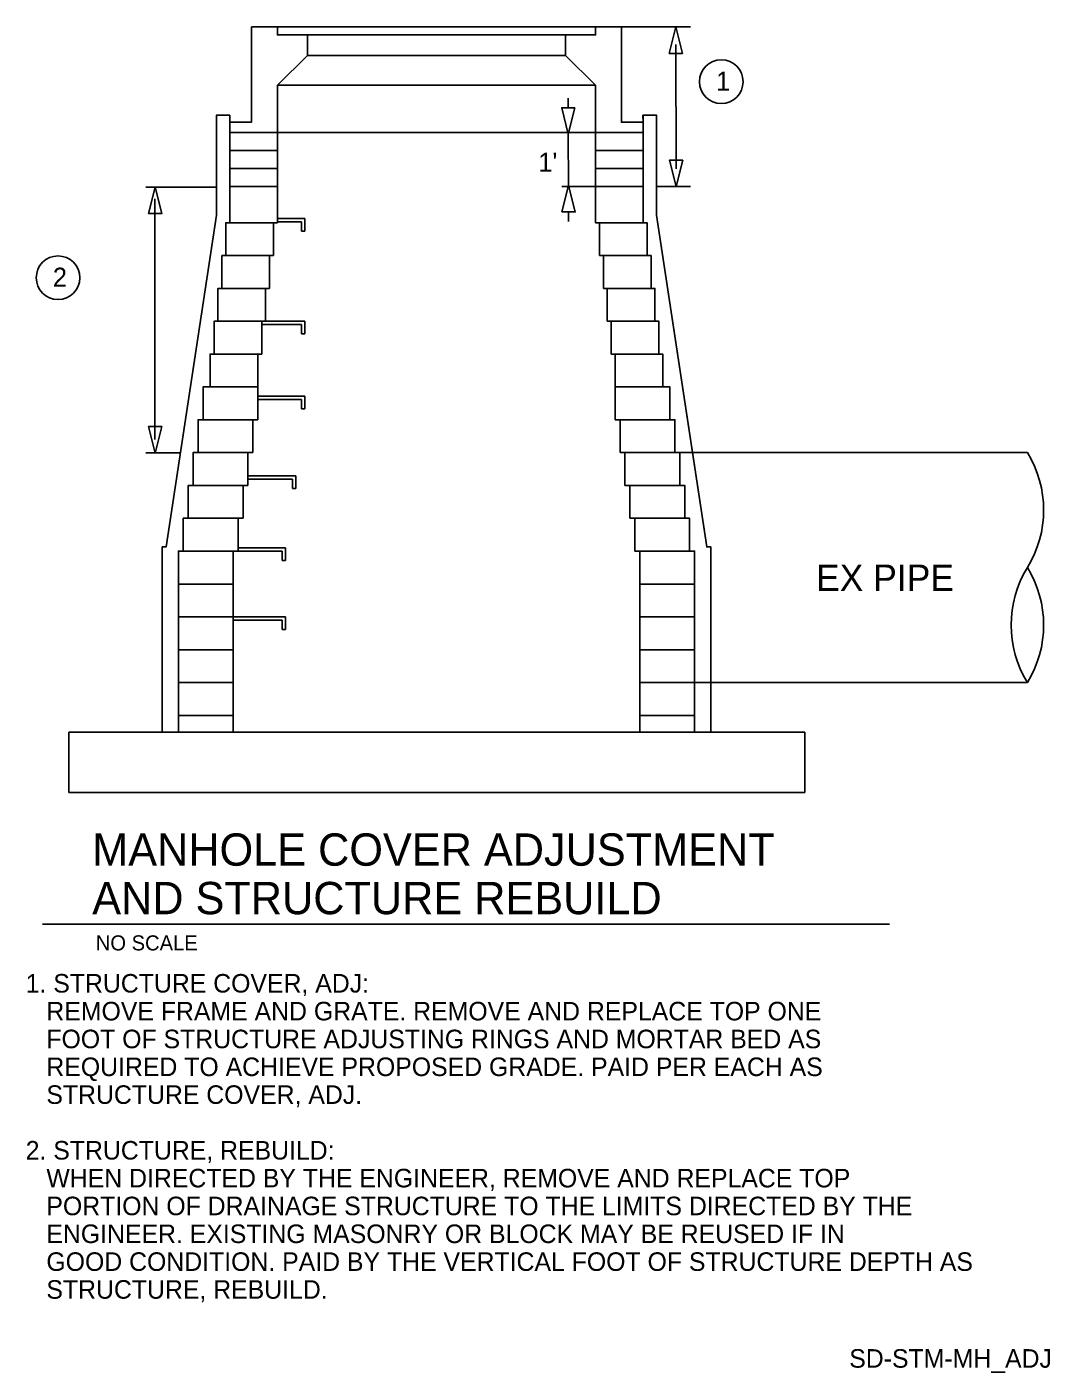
# Model space of a CAD drawing. Extents: x 9854.7 to 9913.9, y 9660.7 to 9738.6.
import ezdxf

# ---------------------------------------------------------------- set-up
doc = ezdxf.new("R2010")
doc.units = 0
for name, color, linetype in [('Default', 7, 'Continuous'), ('G-ANNO-DIMS', 7, 'Continuous'), ('G-ANNO-TEXT', 7, 'Continuous')]:
    doc.layers.add(name, color=color, linetype=linetype)

msp = doc.modelspace()

# ---------------------------------------------------------------- linework, layer by layer
at = {"layer": 'Default'}
for p, q in [((9867.695, 9738.614), (9889.093, 9738.614)), ((9867.695, 9738.614), (9867.695, 9733.099)), ((9869.194, 9738.614), (9869.194, 9738.151)), ((9869.194, 9738.151), (9887.594, 9738.151)), ((9870.927, 9738.151), (9870.927, 9736.97)), ((9885.861, 9738.151), (9885.861, 9736.97)), ((9887.594, 9738.614), (9887.594, 9738.151)), ((9889.093, 9738.614), (9889.093, 9733.099)), ((9869.194, 9735.237), (9870.927, 9736.97)), ((9870.927, 9736.97), (9885.861, 9736.97)), ((9887.594, 9735.237), (9885.861, 9736.97)), ((9869.194, 9735.237), (9887.594, 9735.237)), ((9869.194, 9735.237), (9869.194, 9732.506)), ((9887.594, 9735.237), (9887.594, 9732.506)), ((9865.663, 9727.73), (9865.663, 9733.506)), ((9865.663, 9733.506), (9866.437, 9733.506)), ((9866.437, 9733.506), (9866.437, 9732.506)), ((9891.125, 9733.506), (9890.332, 9733.506)), ((9890.351, 9733.506), (9890.351, 9732.506)), ((9891.125, 9727.73), (9891.125, 9733.506)), ((9867.695, 9733.099), (9866.437, 9733.099)), ((9866.437, 9732.506), (9890.351, 9732.506)), ((9866.437, 9732.506), (9866.437, 9731.463)), ((9869.194, 9731.463), (9869.194, 9732.506)), ((9887.594, 9732.506), (9887.594, 9731.463)), ((9889.093, 9733.099), (9890.351, 9733.099)), ((9890.351, 9733.099), (9890.351, 9732.506)), ((9890.351, 9731.463), (9890.351, 9732.506)), ((9866.437, 9731.463), (9869.194, 9731.463)), ((9866.437, 9731.463), (9866.437, 9730.42)), ((9869.194, 9730.42), (9869.194, 9731.463)), ((9887.594, 9731.463), (9890.351, 9731.463)), ((9887.594, 9731.463), (9887.594, 9730.42)), ((9890.351, 9730.42), (9890.351, 9731.463)), ((9866.437, 9730.42), (9869.194, 9730.42)), ((9866.437, 9730.42), (9866.437, 9729.377)), ((9869.194, 9729.377), (9869.194, 9730.42)), ((9887.594, 9730.42), (9890.351, 9730.42)), ((9887.594, 9730.42), (9887.594, 9729.377)), ((9890.351, 9729.377), (9890.351, 9730.42)), ((9866.437, 9729.377), (9869.194, 9729.377)), ((9866.437, 9729.377), (9866.437, 9728.334)), ((9869.194, 9728.334), (9869.194, 9729.377)), ((9887.594, 9729.377), (9890.351, 9729.377)), ((9887.594, 9729.377), (9887.594, 9728.334)), ((9890.351, 9728.334), (9890.351, 9729.377)), ((9866.437, 9728.334), (9866.437, 9727.291)), ((9869.194, 9727.291), (9869.194, 9728.334)), ((9887.594, 9728.334), (9887.594, 9727.291)), ((9890.351, 9727.291), (9890.351, 9728.334)), ((9862.76, 9708.536), (9865.663, 9727.73)), ((9868.968, 9727.291), (9866.21, 9727.291)), ((9866.21, 9727.291), (9866.21, 9725.391)), ((9866.437, 9727.291), (9869.194, 9727.291)), ((9868.968, 9727.291), (9868.968, 9725.391)), ((9869.194, 9727.531), (9870.788, 9727.531)), ((9869.194, 9727.339), (9870.594, 9727.339)), ((9870.594, 9727.339), (9870.594, 9726.8)), ((9870.788, 9727.531), (9870.788, 9726.8)), ((9887.594, 9727.291), (9890.351, 9727.291)), ((9887.82, 9727.291), (9887.82, 9725.391)), ((9887.82, 9727.291), (9890.578, 9727.291)), ((9890.578, 9727.291), (9890.578, 9725.391)), ((9894.027, 9708.536), (9891.125, 9727.73)), ((9870.594, 9726.8), (9870.788, 9726.8)), ((9868.741, 9725.391), (9865.984, 9725.391)), ((9865.984, 9725.391), (9865.984, 9723.491)), ((9868.968, 9725.391), (9866.21, 9725.391)), ((9868.741, 9725.391), (9868.741, 9723.491)), ((9887.82, 9725.391), (9890.578, 9725.391)), ((9888.047, 9725.391), (9888.047, 9723.491)), ((9888.047, 9725.391), (9890.804, 9725.391)), ((9890.804, 9725.391), (9890.804, 9723.491)), ((9868.515, 9723.491), (9865.757, 9723.491)), ((9865.757, 9723.491), (9865.757, 9721.591)), ((9868.741, 9723.491), (9865.984, 9723.491)), ((9868.515, 9723.491), (9868.515, 9721.591)), ((9888.047, 9723.491), (9890.804, 9723.491)), ((9888.273, 9723.491), (9888.273, 9721.591)), ((9888.273, 9723.491), (9891.031, 9723.491)), ((9891.031, 9723.491), (9891.031, 9721.591)), ((9868.515, 9721.599), (9870.788, 9721.599)), ((9870.788, 9721.599), (9870.788, 9720.868)), ((9868.288, 9721.591), (9865.531, 9721.591)), ((9865.531, 9721.591), (9865.531, 9719.69)), ((9868.515, 9721.591), (9865.757, 9721.591)), ((9868.288, 9721.591), (9868.288, 9719.69)), ((9868.288, 9721.408), (9870.594, 9721.408)), ((9870.594, 9721.408), (9870.594, 9720.868)), ((9870.594, 9720.868), (9870.788, 9720.868)), ((9888.273, 9721.591), (9891.031, 9721.591)), ((9888.5, 9721.591), (9888.5, 9719.69)), ((9888.5, 9721.591), (9891.257, 9721.591)), ((9891.257, 9721.591), (9891.257, 9719.69)), ((9868.062, 9719.69), (9865.304, 9719.69)), ((9865.304, 9719.69), (9865.304, 9717.79)), ((9868.288, 9719.69), (9865.531, 9719.69)), ((9868.062, 9719.69), (9868.062, 9717.79)), ((9888.5, 9719.69), (9891.257, 9719.69)), ((9888.726, 9719.69), (9888.726, 9717.79)), ((9888.726, 9719.69), (9891.484, 9719.69)), ((9891.484, 9719.69), (9891.484, 9717.79)), ((9868.062, 9717.79), (9864.893, 9717.79)), ((9864.893, 9717.79), (9864.893, 9715.89)), ((9868.062, 9717.79), (9868.062, 9715.89)), ((9888.726, 9717.79), (9891.895, 9717.79)), ((9888.726, 9717.79), (9888.726, 9715.89)), ((9891.895, 9717.79), (9891.895, 9715.89)), ((9868.062, 9717.247), (9870.788, 9717.247)), ((9868.062, 9717.055), (9870.594, 9717.055)), ((9870.594, 9717.055), (9870.594, 9716.515)), ((9870.788, 9717.247), (9870.788, 9716.515)), ((9870.594, 9716.515), (9870.788, 9716.515)), ((9867.776, 9715.89), (9864.608, 9715.89)), ((9864.608, 9715.89), (9864.608, 9713.99)), ((9868.062, 9715.89), (9864.893, 9715.89)), ((9867.776, 9715.89), (9867.776, 9713.99)), ((9888.726, 9715.89), (9891.895, 9715.89)), ((9889.012, 9715.89), (9892.18, 9715.89)), ((9889.012, 9715.89), (9889.012, 9713.99)), ((9892.18, 9715.89), (9892.18, 9713.99)), ((9867.491, 9713.99), (9864.322, 9713.99)), ((9864.322, 9713.99), (9864.322, 9712.089)), ((9867.776, 9713.99), (9864.608, 9713.99)), ((9867.491, 9713.99), (9867.491, 9712.089)), ((9889.012, 9713.99), (9892.18, 9713.99)), ((9889.012, 9713.99), (9912.569, 9713.99)), ((9889.297, 9713.99), (9892.465, 9713.99)), ((9889.297, 9713.99), (9889.297, 9712.089)), ((9892.465, 9713.99), (9892.465, 9712.089)), ((9867.491, 9712.648), (9870.255, 9712.648)), ((9867.491, 9712.456), (9870.06, 9712.456)), ((9870.06, 9712.456), (9870.06, 9711.917)), ((9870.255, 9712.648), (9870.255, 9711.917)), ((9867.206, 9712.089), (9864.037, 9712.089)), ((9864.037, 9712.089), (9864.037, 9710.189)), ((9867.491, 9712.089), (9864.322, 9712.089)), ((9867.206, 9712.089), (9867.206, 9710.189)), ((9870.06, 9711.917), (9870.255, 9711.917)), ((9889.297, 9712.089), (9892.465, 9712.089)), ((9889.582, 9712.089), (9892.751, 9712.089)), ((9889.582, 9712.089), (9889.582, 9710.189)), ((9892.751, 9712.089), (9892.751, 9710.189)), ((9866.92, 9710.189), (9863.752, 9710.189)), ((9863.752, 9710.189), (9863.752, 9708.289)), ((9867.206, 9710.189), (9864.037, 9710.189)), ((9866.92, 9710.189), (9866.92, 9708.289)), ((9889.582, 9710.189), (9892.751, 9710.189)), ((9889.867, 9710.189), (9893.036, 9710.189)), ((9889.867, 9710.189), (9889.867, 9708.289)), ((9893.036, 9710.189), (9893.036, 9708.289)), ((9862.53, 9697.827), (9862.53, 9708.536)), ((9862.53, 9708.536), (9862.76, 9708.536)), ((9866.92, 9708.481), (9869.659, 9708.481)), ((9869.659, 9708.481), (9869.659, 9707.749)), ((9894.258, 9708.536), (9894.027, 9708.536)), ((9894.258, 9697.827), (9894.258, 9708.536)), ((9866.635, 9708.289), (9863.467, 9708.289)), ((9863.467, 9708.289), (9863.467, 9706.389)), ((9866.92, 9708.289), (9863.752, 9708.289)), ((9866.635, 9708.289), (9866.635, 9706.389)), ((9866.92, 9708.289), (9869.465, 9708.289)), ((9869.465, 9708.289), (9869.465, 9707.749)), ((9869.465, 9707.749), (9869.659, 9707.749)), ((9889.867, 9708.289), (9893.036, 9708.289)), ((9890.153, 9708.289), (9893.321, 9708.289)), ((9890.153, 9708.289), (9890.153, 9706.389)), ((9893.321, 9708.289), (9893.321, 9706.389)), ((9866.635, 9706.389), (9863.467, 9706.389)), ((9863.467, 9706.389), (9863.467, 9704.488)), ((9866.635, 9706.389), (9866.635, 9704.488)), ((9890.153, 9706.389), (9893.321, 9706.389)), ((9890.153, 9706.389), (9890.153, 9704.488)), ((9893.321, 9706.389), (9893.321, 9704.488)), ((9866.635, 9704.488), (9863.467, 9704.488)), ((9863.467, 9704.488), (9863.467, 9702.588)), ((9866.635, 9704.488), (9866.635, 9702.588)), ((9866.635, 9704.488), (9869.659, 9704.488)), ((9869.659, 9704.488), (9869.659, 9703.757)), ((9890.153, 9704.488), (9893.321, 9704.488)), ((9890.153, 9704.488), (9890.153, 9702.588)), ((9893.321, 9704.488), (9893.321, 9702.588)), ((9866.635, 9704.297), (9869.465, 9704.297)), ((9869.465, 9704.297), (9869.465, 9703.757)), ((9869.465, 9703.757), (9869.659, 9703.757)), ((9866.635, 9702.588), (9863.467, 9702.588)), ((9863.467, 9702.588), (9863.467, 9700.688)), ((9866.635, 9702.588), (9866.635, 9700.688)), ((9890.153, 9702.588), (9893.321, 9702.588)), ((9890.153, 9702.588), (9890.153, 9700.688)), ((9893.321, 9702.588), (9893.321, 9700.688)), ((9866.635, 9700.688), (9863.467, 9700.688)), ((9863.467, 9700.688), (9863.467, 9698.788)), ((9866.635, 9700.688), (9866.635, 9698.788)), ((9890.153, 9700.688), (9893.321, 9700.688)), ((9890.153, 9700.688), (9890.153, 9698.788)), ((9890.153, 9700.688), (9912.569, 9700.688)), ((9893.321, 9700.688), (9893.321, 9698.788)), ((9866.635, 9698.788), (9863.467, 9698.788)), ((9863.467, 9698.788), (9863.467, 9697.827)), ((9866.635, 9698.788), (9866.635, 9697.827)), ((9890.153, 9698.788), (9893.321, 9698.788)), ((9890.153, 9698.788), (9890.153, 9697.827)), ((9893.321, 9698.788), (9893.321, 9697.827)), ((9857.124, 9697.827), (9899.705, 9697.827)), ((9857.124, 9697.827), (9857.124, 9694.335)), ((9899.705, 9697.827), (9899.705, 9694.335)), ((9857.124, 9694.335), (9899.705, 9694.335))]:
    msp.add_line(p, q, dxfattribs=at)
for points in [[(9867.695, 9738.614), (9867.695, 9733.099), (9866.437, 9733.099), (9866.437, 9732.506), (9869.194, 9732.506), (9869.194, 9735.237), (9870.927, 9736.97), (9870.927, 9738.151), (9869.194, 9738.151), (9869.194, 9738.614)], [(9889.093, 9738.614), (9889.093, 9733.099), (9890.351, 9733.099), (9890.351, 9732.506), (9887.594, 9732.506), (9887.594, 9735.237), (9885.861, 9736.97), (9885.861, 9738.151), (9887.594, 9738.151), (9887.594, 9738.614)]]:
    msp.add_lwpolyline(points, close=True, dxfattribs=at)
for points in [[(9887.594, 9738.614), (9869.194, 9738.614), (9869.194, 9738.151), (9870.927, 9738.151), (9885.861, 9738.151), (9887.594, 9738.151), (9887.594, 9738.614)], [(9862.53, 9697.827), (9863.467, 9697.827), (9863.467, 9698.788), (9863.467, 9700.688), (9863.467, 9702.588), (9863.467, 9704.488), (9863.467, 9706.389), (9863.467, 9708.289), (9863.752, 9708.289), (9863.752, 9710.189), (9864.037, 9710.189), (9864.037, 9712.089), (9864.322, 9712.089), (9864.322, 9713.99), (9864.608, 9713.99), (9864.608, 9715.89), (9864.893, 9715.89), (9864.893, 9717.79), (9865.304, 9717.79), (9865.304, 9719.69), (9865.531, 9719.69), (9865.531, 9721.591), (9865.757, 9721.591), (9865.757, 9723.491), (9865.984, 9723.491), (9865.984, 9725.391), (9866.21, 9725.391), (9866.21, 9727.291), (9866.437, 9727.291), (9866.437, 9728.334), (9866.437, 9729.377), (9866.437, 9730.42), (9866.437, 9731.463), (9866.437, 9732.506), (9866.437, 9733.099), (9866.437, 9733.506), (9865.663, 9733.506), (9865.663, 9727.73), (9862.76, 9708.536), (9862.53, 9708.536), (9862.53, 9697.827)], [(9892.18, 9713.99), (9892.465, 9713.99), (9893.203, 9713.99), (9891.125, 9727.73), (9891.125, 9733.506), (9890.332, 9733.506), (9890.34, 9733.099), (9890.351, 9733.099), (9890.351, 9732.506), (9890.351, 9731.463), (9890.351, 9730.42), (9890.351, 9729.377), (9890.351, 9728.334), (9890.351, 9727.291), (9890.578, 9727.291), (9890.578, 9725.391), (9890.804, 9725.391), (9890.804, 9723.491), (9891.031, 9723.491), (9891.031, 9721.591), (9891.257, 9721.591), (9891.257, 9719.69), (9891.484, 9719.69), (9891.484, 9717.79), (9891.895, 9717.79), (9891.895, 9715.89), (9892.18, 9715.89), (9892.18, 9713.99)], [(9893.321, 9700.688), (9894.258, 9700.688), (9894.258, 9708.536), (9894.027, 9708.536), (9893.203, 9713.99), (9892.465, 9713.99), (9892.465, 9712.089), (9892.751, 9712.089), (9892.751, 9710.189), (9893.036, 9710.189), (9893.036, 9708.289), (9893.321, 9708.289), (9893.321, 9706.389), (9893.321, 9704.488), (9893.321, 9702.588), (9893.321, 9700.688)], [(9894.258, 9700.688), (9893.321, 9700.688), (9893.321, 9698.788), (9893.321, 9697.827), (9894.258, 9697.827), (9894.258, 9700.688)]]:
    msp.add_lwpolyline(points, dxfattribs=at)
for centre in [(9894.866, 9735.448), (9856.507, 9724.106)]:
    msp.add_circle(centre, 1.261, dxfattribs=at)
for centre, start, end in [((9907.146, 9710.664), 328.48457, 31.51543), ((9917.993, 9704.013), 148.48457, 211.51543), ((9907.146, 9704.013), 328.48457, 31.51543)]:
    msp.add_arc(centre, 6.362, start, end, dxfattribs=at)
at = {"layer": 'G-ANNO-DIMS'}
for p, q in [((9893.082, 9738.615), (9889.091, 9738.615)), ((9892.231, 9737.593), (9892.256, 9730.4)), ((9886.019, 9733.941), (9886.019, 9734.497)), ((9879.37, 9732.506), (9877.418, 9732.506)), ((9879.37, 9732.506), (9877.418, 9732.506)), ((9879.37, 9732.506), (9877.418, 9732.506)), ((9887.594, 9732.502), (9885.642, 9732.502)), ((9886.019, 9732.408), (9886.034, 9729.447)), ((9865.611, 9729.349), (9861.577, 9729.349)), ((9862.099, 9714.746), (9862.099, 9728.666)), ((9887.594, 9729.377), (9885.642, 9729.377)), ((9893.082, 9729.377), (9891.131, 9729.377)), ((9886.034, 9727.913), (9886.034, 9727.357)), ((9863.529, 9713.977), (9861.577, 9713.977))]:
    msp.add_line(p, q, dxfattribs=at)
for points in [[(9891.847, 9737.082), (9892.231, 9738.615), (9892.614, 9737.082)], [(9886.403, 9733.941), (9886.019, 9732.408), (9885.636, 9733.941)], [(9892.64, 9730.911), (9892.256, 9729.377), (9891.873, 9730.911)], [(9885.651, 9727.913), (9886.034, 9729.447), (9886.417, 9727.913)], [(9861.742, 9727.817), (9862.126, 9729.35), (9862.509, 9727.817)], [(9862.506, 9715.496), (9862.123, 9713.963), (9861.74, 9715.496)]]:
    msp.add_lwpolyline(points, close=True, dxfattribs=at)
at = {"layer": 'G-ANNO-TEXT'}
msp.add_line((9855.608, 9686.702), (9904.59, 9686.702), dxfattribs=at)

# ---------------------------------------------------------------- texts
at = {"layer": 'Default'}
for s, height, p in [('1', 1.104, (9894.563, 9734.926)), ("1'", 1.104, (9884.28, 9730.236)), ('2', 1.104, (9856.204, 9723.584)), ('EX PIPE', 1.5333, (9900.347, 9705.98)), ('1. STRUCTURE COVER, ADJ:', 1.07332, (9854.636, 9682.754)), ('   REMOVE FRAME AND GRATE. REMOVE AND REPLACE TOP ONE', 1.07332, (9854.636, 9681.144)), ('   FOOT OF STRUCTURE ADJUSTING RINGS AND MORTAR BED AS ', 1.07332, (9854.636, 9679.534)), ('   REQUIRED TO ACHIEVE PROPOSED GRADE. PAID PER EACH AS', 1.07332, (9854.636, 9677.924)), ('   STRUCTURE COVER, ADJ.', 1.07332, (9854.636, 9676.314)), ('2. STRUCTURE, REBUILD:', 1.07332, (9854.636, 9673.094)), ('   WHEN DIRECTED BY THE ENGINEER, REMOVE AND REPLACE TOP', 1.07332, (9854.636, 9671.484)), ('   PORTION OF DRAINAGE STRUCTURE TO THE LIMITS DIRECTED BY THE', 1.07332, (9854.636, 9669.874)), ('   ENGINEER. EXISTING MASONRY OR BLOCK MAY BE REUSED IF IN', 1.07332, (9854.636, 9668.264)), ('   GOOD CONDITION. PAID BY THE VERTICAL FOOT OF STRUCTURE DEPTH AS ', 1.07332, (9854.636, 9666.654)), ('   STRUCTURE, REBUILD.', 1.07332, (9854.636, 9665.044)), ('SD-STM-MH_ADJ', 1.07332, (9902.267, 9661.053))]:
    msp.add_text(s, height=height, dxfattribs=at).set_placement(p)
at = {"layer": 'G-ANNO-TEXT'}
for s, height, p in [('MANHOLE COVER ADJUSTMENT ', 1.8704, (9858.484, 9690.092)), ('AND STRUCTURE REBUILD', 1.8704, (9858.484, 9687.286)), ('NO SCALE', 0.872, (9858.689, 9685.192))]:
    msp.add_text(s, height=height, dxfattribs=at).set_placement(p)

doc.saveas('drawing.dxf')
